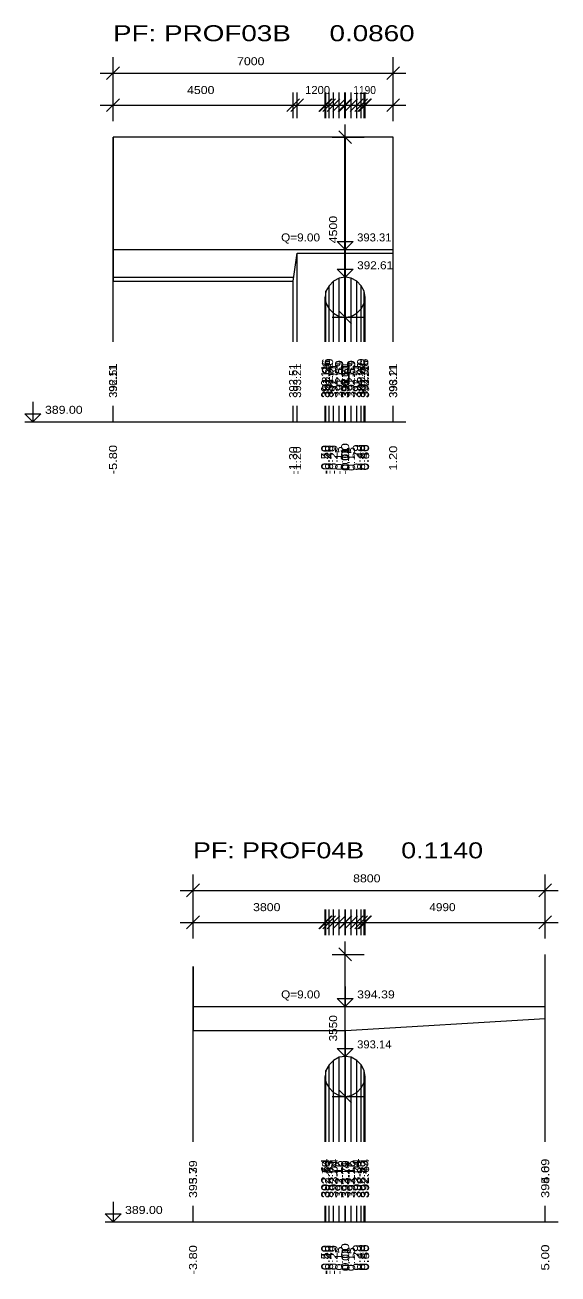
# Model space of a CAD drawing. Extents: x 7 to 442, y -393 to 441.
# Drawn here: x 293.63 to 306.95, y 175.9 to 207.12 of the extents above; entities that cross this region are included whole.
import ezdxf

# ---------------------------------------------------------------- set-up
doc = ezdxf.new("R2010")
doc.units = 0
doc.header["$LTSCALE"] = 0.08
doc.layers.add('7', color=7, linetype='Continuous', lineweight=13)

msp = doc.modelspace()

# ---------------------------------------------------------------- linework, layer by layer
at = {"layer": '7'}
for p, q in [((295.675, 205.753), (295.995, 206.073)), ((295.835, 204.713), (295.835, 206.313)), ((302.675, 205.753), (302.995, 206.073)), ((302.835, 204.713), (302.835, 206.313)), ((295.515, 205.913), (303.155, 205.913)), ((295.835, 204.793), (295.835, 205.433)), ((295.835, 204.793), (295.835, 205.433)), ((300.335, 204.793), (300.335, 205.433)), ((300.435, 204.793), (300.435, 205.433)), ((301.135, 204.793), (301.135, 205.433)), ((301.155, 204.793), (301.155, 205.433)), ((301.155, 204.793), (301.155, 205.433)), ((301.235, 204.793), (301.235, 205.433)), ((301.235, 204.793), (301.235, 205.433)), ((301.345, 204.793), (301.345, 205.433)), ((301.345, 204.793), (301.345, 205.433)), ((301.485, 204.793), (301.485, 205.433)), ((301.485, 204.793), (301.485, 205.433)), ((301.625, 204.793), (301.625, 205.433)), ((301.635, 204.793), (301.635, 205.433)), ((301.635, 204.793), (301.635, 205.433)), ((301.635, 204.793), (301.635, 205.433)), ((301.645, 204.793), (301.645, 205.433)), ((301.645, 204.793), (301.645, 205.433)), ((301.645, 204.793), (301.645, 205.433)), ((301.785, 204.793), (301.785, 205.433)), ((301.785, 204.793), (301.785, 205.433)), ((301.925, 204.793), (301.925, 205.433)), ((301.925, 204.793), (301.925, 205.433)), ((302.035, 204.793), (302.035, 205.433)), ((302.035, 204.793), (302.035, 205.433)), ((302.115, 204.793), (302.115, 205.433)), ((302.115, 204.793), (302.115, 205.433)), ((302.135, 204.793), (302.135, 205.433)), ((302.835, 204.793), (302.835, 205.433)), ((302.835, 204.793), (302.835, 205.433)), ((295.675, 204.953), (295.995, 205.273)), ((295.675, 204.953), (295.995, 205.273)), ((300.175, 204.953), (300.495, 205.273)), ((300.275, 204.953), (300.595, 205.273)), ((300.975, 204.953), (301.295, 205.273)), ((300.995, 204.953), (301.315, 205.273)), ((300.995, 204.953), (301.315, 205.273)), ((301.075, 204.953), (301.395, 205.273)), ((301.075, 204.953), (301.395, 205.273)), ((301.185, 204.953), (301.505, 205.273)), ((301.185, 204.953), (301.505, 205.273)), ((301.325, 204.953), (301.645, 205.273)), ((301.325, 204.953), (301.645, 205.273)), ((301.465, 204.953), (301.785, 205.273)), ((301.475, 204.953), (301.795, 205.273)), ((301.475, 204.953), (301.795, 205.273)), ((301.475, 204.953), (301.795, 205.273)), ((301.485, 204.953), (301.805, 205.273)), ((301.485, 204.953), (301.805, 205.273)), ((301.485, 204.953), (301.805, 205.273)), ((301.625, 204.953), (301.945, 205.273)), ((301.625, 204.953), (301.945, 205.273)), ((301.765, 204.953), (302.085, 205.273)), ((301.765, 204.953), (302.085, 205.273)), ((301.875, 204.953), (302.195, 205.273)), ((301.875, 204.953), (302.195, 205.273)), ((301.955, 204.953), (302.275, 205.273)), ((301.955, 204.953), (302.275, 205.273)), ((301.975, 204.953), (302.295, 205.273)), ((302.675, 204.953), (302.995, 205.273)), ((302.675, 204.953), (302.995, 205.273)), ((295.515, 205.113), (303.155, 205.113)), ((301.635, 199.653), (301.635, 204.633)), ((295.835, 199.2), (295.835, 204.313)), ((301.315, 204.313), (302.115, 204.313)), ((301.795, 204.153), (301.475, 204.473)), ((301.625, 199.2), (301.625, 204.313)), ((301.645, 199.2), (301.645, 204.313)), ((302.835, 199.2), (302.835, 204.313)), ((295.835, 201.509), (302.835, 201.509)), ((300.435, 199.2), (300.435, 201.413)), ((301.635, 199.2), (301.635, 201.413)), ((301.645, 199.2), (301.645, 201.413)), ((302.835, 199.2), (302.835, 201.413)), ((295.835, 200.813), (300.349, 200.813)), ((301.485, 199.2), (301.485, 200.793)), ((301.635, 199.2), (301.635, 200.813)), ((301.645, 199.2), (301.645, 200.813)), ((301.785, 199.2), (301.785, 200.793)), ((295.835, 199.2), (295.835, 200.713)), ((300.335, 199.2), (300.335, 200.713)), ((301.155, 199.2), (301.155, 200.463)), ((301.235, 199.2), (301.235, 200.603)), ((301.345, 199.2), (301.345, 200.713)), ((301.925, 199.2), (301.925, 200.713)), ((302.035, 199.2), (302.035, 200.603)), ((302.115, 199.2), (302.115, 200.463)), ((301.135, 199.2), (301.135, 200.313)), ((301.155, 199.2), (301.155, 200.163)), ((302.115, 199.2), (302.115, 200.163)), ((302.135, 199.2), (302.135, 200.313)), ((301.235, 199.2), (301.235, 200.023)), ((301.315, 199.813), (302.115, 199.813)), ((301.345, 199.2), (301.345, 199.913)), ((301.795, 199.653), (301.475, 199.973)), ((301.485, 199.2), (301.485, 199.833)), ((301.635, 199.2), (301.635, 199.813)), ((301.785, 199.2), (301.785, 199.833)), ((301.925, 199.2), (301.925, 199.913)), ((302.035, 199.2), (302.035, 200.023)), ((295.835, 197.2), (295.835, 197.6)), ((295.835, 197.2), (295.835, 197.6)), ((300.335, 197.2), (300.335, 197.6)), ((300.435, 197.2), (300.435, 197.6)), ((301.135, 197.2), (301.135, 197.6)), ((301.155, 197.2), (301.155, 197.6)), ((301.155, 197.2), (301.155, 197.6)), ((301.235, 197.2), (301.235, 197.6)), ((301.235, 197.2), (301.235, 197.6)), ((301.345, 197.2), (301.345, 197.6)), ((301.345, 197.2), (301.345, 197.6)), ((301.485, 197.2), (301.485, 197.6)), ((301.485, 197.2), (301.485, 197.6)), ((301.625, 197.2), (301.625, 197.6)), ((301.635, 197.2), (301.635, 197.6)), ((301.635, 197.2), (301.635, 197.6)), ((301.635, 197.2), (301.635, 197.6)), ((301.645, 197.2), (301.645, 197.6)), ((301.645, 197.2), (301.645, 197.6)), ((301.645, 197.2), (301.645, 197.6)), ((301.785, 197.2), (301.785, 197.6)), ((301.785, 197.2), (301.785, 197.6)), ((301.925, 197.2), (301.925, 197.6)), ((301.925, 197.2), (301.925, 197.6)), ((302.035, 197.2), (302.035, 197.6)), ((302.035, 197.2), (302.035, 197.6)), ((302.115, 197.2), (302.115, 197.6)), ((302.115, 197.2), (302.115, 197.6)), ((302.135, 197.2), (302.135, 197.6)), ((302.835, 197.2), (302.835, 197.6)), ((302.835, 197.2), (302.835, 197.6)), ((293.635, 197.2), (303.155, 197.2)), ((297.835, 184.289), (297.835, 185.889)), ((306.635, 184.289), (306.635, 185.889)), ((297.515, 185.489), (306.955, 185.489)), ((297.675, 185.329), (297.995, 185.649)), ((306.475, 185.329), (306.795, 185.649)), ((297.675, 184.529), (297.995, 184.849)), ((297.675, 184.529), (297.995, 184.849)), ((297.835, 184.369), (297.835, 185.009)), ((297.835, 184.369), (297.835, 185.009)), ((300.975, 184.529), (301.295, 184.849)), ((300.995, 184.529), (301.315, 184.849)), ((300.995, 184.529), (301.315, 184.849)), ((301.075, 184.529), (301.395, 184.849)), ((301.075, 184.529), (301.395, 184.849)), ((301.135, 184.369), (301.135, 185.009)), ((301.155, 184.369), (301.155, 185.009)), ((301.155, 184.369), (301.155, 185.009)), ((301.185, 184.529), (301.505, 184.849)), ((301.185, 184.529), (301.505, 184.849)), ((301.235, 184.369), (301.235, 185.009)), ((301.235, 184.369), (301.235, 185.009)), ((301.325, 184.529), (301.645, 184.849)), ((301.325, 184.529), (301.645, 184.849)), ((301.345, 184.369), (301.345, 185.009)), ((301.345, 184.369), (301.345, 185.009)), ((301.475, 184.529), (301.795, 184.849)), ((301.475, 184.529), (301.795, 184.849)), ((301.475, 184.529), (301.795, 184.849)), ((301.485, 184.369), (301.485, 185.009)), ((301.485, 184.369), (301.485, 185.009)), ((301.485, 184.529), (301.805, 184.849)), ((301.485, 184.529), (301.805, 184.849)), ((301.625, 184.529), (301.945, 184.849)), ((301.625, 184.529), (301.945, 184.849)), ((301.635, 184.369), (301.635, 185.009)), ((301.635, 184.369), (301.635, 185.009)), ((301.635, 184.369), (301.635, 185.009)), ((301.645, 184.369), (301.645, 185.009)), ((301.645, 184.369), (301.645, 185.009)), ((301.765, 184.529), (302.085, 184.849)), ((301.765, 184.529), (302.085, 184.849)), ((301.785, 184.369), (301.785, 185.009)), ((301.785, 184.369), (301.785, 185.009)), ((301.875, 184.529), (302.195, 184.849)), ((301.875, 184.529), (302.195, 184.849)), ((301.925, 184.369), (301.925, 185.009)), ((301.925, 184.369), (301.925, 185.009)), ((301.955, 184.529), (302.275, 184.849)), ((301.955, 184.529), (302.275, 184.849)), ((301.975, 184.529), (302.295, 184.849)), ((302.035, 184.369), (302.035, 185.009)), ((302.035, 184.369), (302.035, 185.009)), ((302.115, 184.369), (302.115, 185.009)), ((302.115, 184.369), (302.115, 185.009)), ((302.135, 184.369), (302.135, 185.009)), ((306.475, 184.529), (306.795, 184.849)), ((306.475, 184.529), (306.795, 184.849)), ((306.635, 184.369), (306.635, 185.009)), ((306.635, 184.369), (306.635, 185.009)), ((297.515, 184.689), (306.955, 184.689)), ((301.635, 180.179), (301.635, 184.209)), ((301.315, 183.889), (302.115, 183.889)), ((301.795, 183.729), (301.475, 184.049)), ((306.635, 179.2), (306.635, 183.889)), ((297.835, 179.2), (297.835, 183.589)), ((297.835, 182.588), (306.635, 182.588)), ((306.635, 179.2), (306.635, 182.289)), ((297.835, 179.2), (297.835, 181.989)), ((301.635, 179.2), (301.635, 181.989)), ((301.645, 179.2), (301.645, 181.989)), ((301.235, 179.2), (301.235, 181.129)), ((301.345, 179.2), (301.345, 181.239)), ((301.485, 179.2), (301.485, 181.319)), ((301.635, 179.2), (301.635, 181.339)), ((301.635, 181.339), (301.645, 181.339)), ((301.645, 179.2), (301.645, 181.339)), ((301.785, 179.2), (301.785, 181.319)), ((301.925, 179.2), (301.925, 181.239)), ((302.035, 179.2), (302.035, 181.129)), ((301.135, 179.2), (301.135, 180.839)), ((301.155, 179.2), (301.155, 180.989)), ((302.115, 179.2), (302.115, 180.989)), ((302.135, 179.2), (302.135, 180.839)), ((301.155, 179.2), (301.155, 180.689)), ((301.235, 179.2), (301.235, 180.549)), ((301.795, 180.179), (301.475, 180.499)), ((302.035, 179.2), (302.035, 180.549)), ((302.115, 179.2), (302.115, 180.689)), ((301.315, 180.339), (302.115, 180.339)), ((301.345, 179.2), (301.345, 180.439)), ((301.485, 179.2), (301.485, 180.359)), ((301.635, 179.2), (301.635, 180.339)), ((301.785, 179.2), (301.785, 180.359)), ((301.925, 179.2), (301.925, 180.439)), ((297.835, 177.2), (297.835, 177.6)), ((297.835, 177.2), (297.835, 177.6)), ((301.135, 177.2), (301.135, 177.6)), ((301.155, 177.2), (301.155, 177.6)), ((301.155, 177.2), (301.155, 177.6)), ((301.235, 177.2), (301.235, 177.6)), ((301.235, 177.2), (301.235, 177.6)), ((301.345, 177.2), (301.345, 177.6)), ((301.345, 177.2), (301.345, 177.6)), ((301.485, 177.2), (301.485, 177.6)), ((301.485, 177.2), (301.485, 177.6)), ((301.635, 177.2), (301.635, 177.6)), ((301.635, 177.2), (301.635, 177.6)), ((301.635, 177.2), (301.635, 177.6)), ((301.645, 177.2), (301.645, 177.6)), ((301.645, 177.2), (301.645, 177.6)), ((301.785, 177.2), (301.785, 177.6)), ((301.785, 177.2), (301.785, 177.6)), ((301.925, 177.2), (301.925, 177.6)), ((301.925, 177.2), (301.925, 177.6)), ((302.035, 177.2), (302.035, 177.6)), ((302.035, 177.2), (302.035, 177.6)), ((302.115, 177.2), (302.115, 177.6)), ((302.115, 177.2), (302.115, 177.6)), ((302.135, 177.2), (302.135, 177.6)), ((306.635, 177.2), (306.635, 177.6)), ((306.635, 177.2), (306.635, 177.6)), ((295.635, 177.2), (306.955, 177.2))]:
    msp.add_line(p, q, dxfattribs=at)
for points in [[(301.625, 204.313), (295.835, 204.313), (295.835, 200.713), (300.335, 200.713), (300.435, 201.413), (301.635, 201.413), (301.635, 200.813), (301.485, 200.793), (301.345, 200.713), (301.235, 200.603), (301.155, 200.463), (301.135, 200.313), (301.155, 200.163), (301.235, 200.023), (301.345, 199.913), (301.485, 199.833), (301.635, 199.813), (301.785, 199.833), (301.925, 199.913), (302.035, 200.023), (302.115, 200.163), (302.135, 200.313), (302.115, 200.463), (302.035, 200.603), (301.925, 200.713), (301.785, 200.793), (301.645, 200.813), (301.645, 201.413), (302.835, 201.413), (302.835, 204.313), (301.645, 204.313)], [(301.635, 202.009), (301.635, 201.509), (301.435, 201.709), (301.835, 201.709), (301.635, 201.509)], [(301.635, 201.313), (301.635, 200.813), (301.435, 201.013), (301.835, 201.013), (301.635, 200.813), (301.645, 200.813)], [(293.835, 197.7), (293.835, 197.2), (293.635, 197.4), (294.035, 197.4), (293.835, 197.2)], [(297.835, 183.589), (297.835, 181.989), (301.635, 181.989), (301.635, 181.339), (301.485, 181.319), (301.345, 181.239), (301.235, 181.129), (301.155, 180.989), (301.135, 180.839), (301.155, 180.689), (301.235, 180.549), (301.345, 180.439), (301.485, 180.359), (301.635, 180.339), (301.785, 180.359), (301.925, 180.439), (302.035, 180.549), (302.115, 180.689), (302.135, 180.839), (302.115, 180.989), (302.035, 181.129), (301.925, 181.239), (301.785, 181.319), (301.645, 181.339), (301.645, 181.989), (306.635, 182.289), (306.635, 183.889)], [(301.635, 183.088), (301.635, 182.588), (301.435, 182.788), (301.835, 182.788), (301.635, 182.588)], [(301.635, 181.839), (301.635, 181.339), (301.435, 181.539), (301.835, 181.539), (301.635, 181.339)], [(295.835, 177.7), (295.835, 177.2), (295.635, 177.4), (296.035, 177.4), (295.835, 177.2)]]:
    msp.add_lwpolyline(points, dxfattribs=at)

# ---------------------------------------------------------------- texts
for s, height, width, p in [('PF: PROF03B     0.0860', 0.4, 1.3, (295.835, 206.713)), ('7000', 0.2, 1.15, (298.935, 206.113)), ('4500', 0.2, 1.15, (297.685, 205.393)), ('1200', 0.2, 1.05, (300.635, 205.393)), ('1190', 0.2, 0.95, (301.84, 205.393)), ('Q=9.00', 0.2, 1.1, (300.035, 201.709)), ('393.31', 0.2, 1.05, (301.935, 201.709)), ('392.61', 0.2, 1.1, (301.935, 201.013)), ('389.00', 0.2, 1.15, (294.135, 197.4)), ('PF: PROF04B     0.1140', 0.4, 1.25, (297.835, 186.289)), ('8800', 0.2, 1.15, (301.835, 185.689)), ('3800', 0.2, 1.15, (299.335, 184.969)), ('4990', 0.2, 1.1, (303.74, 184.969)), ('Q=9.00', 0.2, 1.1, (300.035, 182.788)), ('394.39', 0.2, 1.15, (301.935, 182.788)), ('393.14', 0.2, 1.05, (301.935, 181.539)), ('389.00', 0.2, 1.15, (296.135, 177.4))]:
    msp.add_text(s, height=height, dxfattribs=dict(at, width=width)).set_placement(p)
for s, width, p in [('4500', 1.15, (301.435, 201.663)), ('392.51 ', 1.05, (295.935, 197.8)), ('392.51 ', 1.05, (300.435, 197.8)), ('393.21 ', 1.05, (300.535, 197.8)), ('392.26 ', 1.2, (301.255, 197.8)), ('391.96 ', 1.15, (301.255, 197.8)), ('392.40 ', 1.2, (301.335, 197.8)), ('391.82 ', 1.1, (301.335, 197.8)), ('392.51 ', 1.05, (301.445, 197.8)), ('392.59 ', 1.15, (301.585, 197.8)), ('391.63 ', 1.1, (301.585, 197.8)), ('392.61 ', 1.1, (301.735, 197.8)), ('393.21 ', 1.05, (301.735, 197.8)), ('392.61 ', 1.1, (301.745, 197.8)), ('393.21 ', 1.05, (301.745, 197.8)), ('392.59 ', 1.15, (301.885, 197.8)), ('391.63 ', 1.1, (301.885, 197.8)), ('392.51 ', 1.05, (302.025, 197.8)), ('392.40 ', 1.2, (302.135, 197.8)), ('391.82 ', 1.1, (302.135, 197.8)), ('392.26 ', 1.2, (302.215, 197.8)), ('391.96 ', 1.15, (302.215, 197.8)), ('393.21 ', 1.05, (302.935, 197.8)), (' -5.80 ', 1.2, (295.935, 195.8)), (' -5.80 ', 1.2, (295.935, 195.8)), (' -1.30 ', 1.15, (300.435, 195.8)), (' -1.20 ', 1.15, (300.535, 195.8)), (' -0.50 ', 1.2, (301.235, 195.8)), (' -0.48 ', 1.2, (301.255, 195.8)), (' -0.48 ', 1.2, (301.255, 195.8)), (' -0.40 ', 1.2, (301.335, 195.8)), (' -0.40 ', 1.2, (301.335, 195.8)), (' -0.29 ', 1.2, (301.445, 195.8)), (' -0.29 ', 1.2, (301.445, 195.8)), (' -0.15 ', 1.15, (301.585, 195.8)), (' -0.15 ', 1.15, (301.585, 195.8)), (' -0.01 ', 1.1, (301.725, 195.8)), ('  0.00 ', 1.3, (301.735, 195.8)), ('  0.00 ', 1.3, (301.735, 195.8)), ('  0.00 ', 1.3, (301.735, 195.8)), ('  0.01 ', 1.15, (301.745, 195.8)), ('  0.01 ', 1.15, (301.745, 195.8)), ('  0.01 ', 1.15, (301.745, 195.8)), ('  0.15 ', 1.15, (301.885, 195.8)), ('  0.15 ', 1.15, (301.885, 195.8)), ('  0.29 ', 1.25, (302.025, 195.8)), ('  0.29 ', 1.25, (302.025, 195.8)), ('  0.40 ', 1.25, (302.135, 195.8)), ('  0.40 ', 1.25, (302.135, 195.8)), ('  0.48 ', 1.25, (302.215, 195.8)), ('  0.48 ', 1.25, (302.215, 195.8)), ('  0.50 ', 1.25, (302.235, 195.8)), ('  1.20 ', 1.2, (302.935, 195.8)), ('  1.20 ', 1.2, (302.935, 195.8)), ('3550', 1.1, (301.435, 181.714)), ('395.39 ', 1.15, (297.935, 177.8)), ('393.79 ', 1.15, (297.935, 177.8)), ('392.64 ', 1.2, (301.235, 177.8)), ('392.79 ', 1.15, (301.255, 177.8)), ('392.49 ', 1.15, (301.255, 177.8)), ('392.35 ', 1.15, (301.335, 177.8)), ('392.93 ', 1.15, (301.335, 177.8)), ('393.04 ', 1.2, (301.445, 177.8)), ('392.24 ', 1.15, (301.445, 177.8)), ('392.16 ', 1.15, (301.585, 177.8)), ('393.12 ', 1.1, (301.585, 177.8)), ('393.79 ', 1.15, (301.735, 177.8)), ('393.14 ', 1.1, (301.735, 177.8)), ('392.14 ', 1.1, (301.735, 177.8)), ('393.79 ', 1.15, (301.745, 177.8)), ('393.14 ', 1.1, (301.745, 177.8)), ('392.16 ', 1.15, (301.885, 177.8)), ('393.12 ', 1.1, (301.885, 177.8)), ('393.04 ', 1.2, (302.025, 177.8)), ('392.24 ', 1.15, (302.025, 177.8)), ('392.35 ', 1.15, (302.135, 177.8)), ('392.93 ', 1.15, (302.135, 177.8)), ('392.49 ', 1.15, (302.215, 177.8)), ('392.79 ', 1.15, (302.215, 177.8)), ('392.64 ', 1.2, (302.235, 177.8)), ('394.09 ', 1.2, (306.735, 177.8)), ('395.69 ', 1.2, (306.735, 177.8)), (' -3.80 ', 1.2, (297.935, 175.8)), (' -3.80 ', 1.2, (297.935, 175.8)), (' -0.50 ', 1.2, (301.235, 175.8)), (' -0.48 ', 1.2, (301.255, 175.8)), (' -0.48 ', 1.2, (301.255, 175.8)), (' -0.40 ', 1.2, (301.335, 175.8)), (' -0.40 ', 1.2, (301.335, 175.8)), (' -0.29 ', 1.2, (301.445, 175.8)), (' -0.29 ', 1.2, (301.445, 175.8)), (' -0.15 ', 1.15, (301.585, 175.8)), (' -0.15 ', 1.15, (301.585, 175.8)), ('  0.00 ', 1.3, (301.735, 175.8)), ('  0.00 ', 1.3, (301.735, 175.8)), ('  0.00 ', 1.3, (301.735, 175.8)), ('  0.01 ', 1.15, (301.745, 175.8)), ('  0.01 ', 1.15, (301.745, 175.8)), ('  0.15 ', 1.15, (301.885, 175.8)), ('  0.15 ', 1.15, (301.885, 175.8)), ('  0.29 ', 1.25, (302.025, 175.8)), ('  0.29 ', 1.25, (302.025, 175.8)), ('  0.40 ', 1.25, (302.135, 175.8)), ('  0.40 ', 1.25, (302.135, 175.8)), ('  0.48 ', 1.25, (302.215, 175.8)), ('  0.48 ', 1.25, (302.215, 175.8)), ('  0.50 ', 1.25, (302.235, 175.8)), ('  5.00 ', 1.25, (306.735, 175.8)), ('  5.00 ', 1.25, (306.735, 175.8))]:
    msp.add_text(s, height=0.2, rotation=90, dxfattribs=dict(at, width=width)).set_placement(p)
for s, p in [('396.11 ', (295.935, 197.8)), ('392.11 ', (301.235, 197.8)), ('391.71 ', (301.445, 197.8)), ('396.11 ', (301.725, 197.8)), ('391.61 ', (301.735, 197.8)), ('396.11 ', (301.745, 197.8)), ('391.71 ', (302.025, 197.8)), ('392.11 ', (302.235, 197.8)), ('396.11 ', (302.935, 197.8))]:
    msp.add_text(s, height=0.2, rotation=90, dxfattribs=at).set_placement(p)

doc.saveas('drawing.dxf')
